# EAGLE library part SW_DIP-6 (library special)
DIP SWITCH
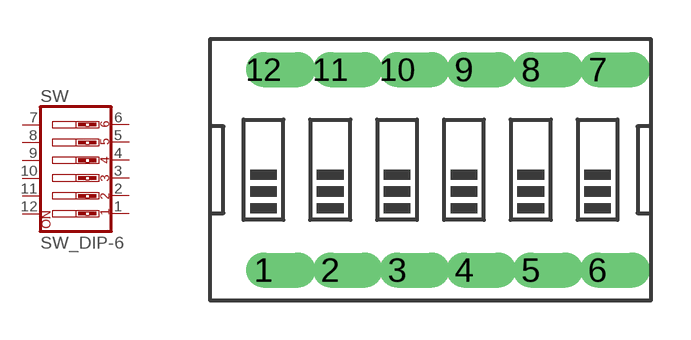
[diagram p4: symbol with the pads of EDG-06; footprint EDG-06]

Designator prefix SW

## SW_DIP-6  [EDG-06]
1  1  pas
2  2  pas
3  3  pas
4  4  pas
5  5  pas
6  6  pas
7  7  pas
8  8  pas
9  9  pas
10  10  pas
11  11  pas
12  12  pas

## Footprint EDG-06 (pad centres in mm)
DIP SWITCH
drill 0.813 offset: 1 -6.35,-3.81; 2 -3.81,-3.81; 3 -1.27,-3.81; 4 1.27,-3.81; 5 3.81,-3.81; 6 6.35,-3.81; 7 6.35,3.81; 8 3.81,3.81; 9 1.27,3.81; 10 -1.27,3.81; 11 -3.81,3.81; 12 -6.35,3.81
